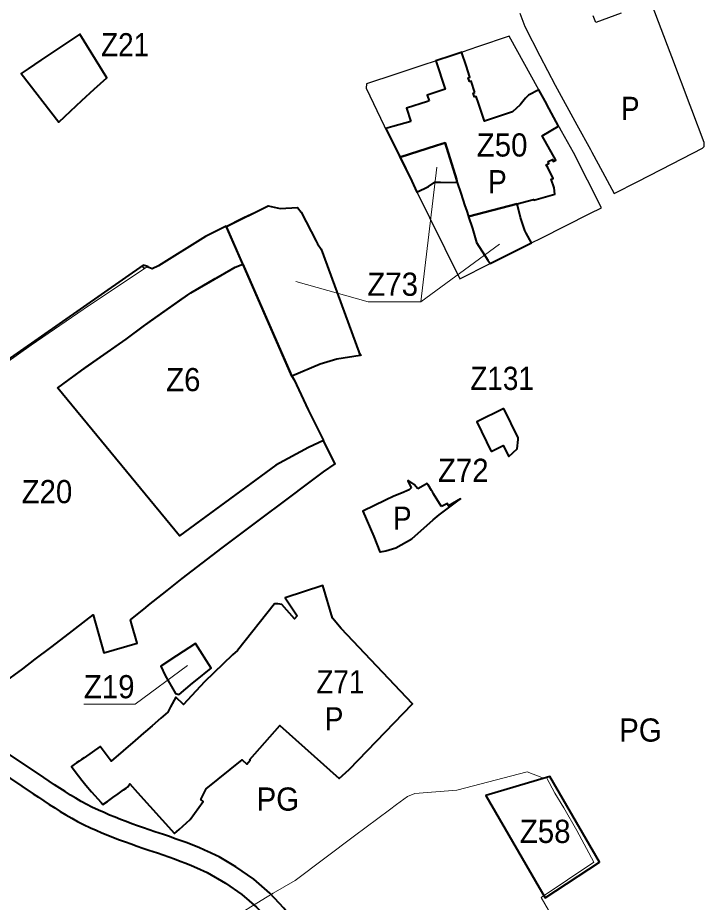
# Model space of a CAD drawing. Extents: x -650276 to -642489, y -1074425 to -1066658.
# Drawn here: x -648043 to -647332, y -1071600 to -1070685 of the extents above; entities that cross this region are included whole.
import ezdxf

# ---------------------------------------------------------------- set-up
doc = ezdxf.new("R2010")
doc.units = 0
doc.header["$LTSCALE"] = 9.6
for name, color, linetype, lineweight in [('1', 7, 'Continuous', 13), ('42', 7, 'Continuous', 25), ('44', 7, 'Continuous', 40), ('45', 7, 'Continuous', 40), ('46', 7, 'Continuous', 13), ('60', 7, 'Continuous', 35)]:
    doc.layers.add(name, color=color, linetype=linetype, lineweight=lineweight)

msp = doc.modelspace()

# ---------------------------------------------------------------- linework, layer by layer
at = {"layer": '1'}
msp.add_line((-647632, -1071487.54), (-647588.48, -1071484.23), dxfattribs=at)
for points in [[(-648084.716, -1071062.607), (-648029.353, -1071023.703), (-647969.116, -1070982.149), (-647909.42, -1070942.63), (-647904.13, -1070944.78), (-647897.76, -1070941.62), (-647848.89, -1070911.21), (-647809.74, -1070891.31), (-647790.016, -1070882.333), (-647783.95, -1070879.58), (-647771.47, -1070882.27), (-647753.81, -1070881.3), (-647749.75, -1070886.1), (-647741.21, -1070902.78), (-647734.48, -1070915.94), (-647732.97, -1070918.87), (-647729.27, -1070924.35), (-647724.603, -1070936.951), (-647701.45, -1070999.4), (-647690.22, -1071030.28), (-647687.41, -1071034.25), (-647688.9, -1071034.18), (-647712.74, -1071037.99), (-647730.17, -1071043.21), (-647759.52, -1071055.67), (-647757.19, -1071059.66), (-647742.64, -1071090.72), (-647726.74, -1071122.48), (-647722.51, -1071130.93), (-647719.73, -1071136.48), (-647714.71, -1071146.51), (-647720.85, -1071150.41), (-647750.34, -1071172.5), (-647756.03, -1071176.76), (-647820.78, -1071225.25), (-647873.25, -1071265.17), (-647888.77, -1071277.56), (-647907.92, -1071292.84), (-647910.73, -1071295.08), (-647926.69, -1071307.81), (-647919.88, -1071332.23), (-647954.38, -1071342)], [(-647954.38, -1071342), (-647965.26, -1071302.86), (-647994.31, -1071325.03), (-648009.31, -1071336.48), (-648025.39, -1071348.76), (-648038.18, -1071358.51), (-648060.01, -1071374.69)], [(-647588.48, -1071484.23), (-647515.87, -1071465.25), (-647498.8, -1071471.94), (-647495.85, -1071471.06), (-647486.94, -1071487.42), (-647477.86, -1071502.65), (-647464.47, -1071526.06), (-647446.68, -1071558.91), (-647501.11, -1071595.45), (-647493.6, -1071608.5)], [(-648086.68, -1071669.2), (-648027.69, -1071748), (-647993.77, -1071766.7), (-647898.22, -1071694.24), (-647875.8, -1071654.22), (-647865.84, -1071646.51), (-647856.11, -1071638.98), (-647845.78, -1071631.97), (-647823.51, -1071618.28), (-647808.56, -1071609.1), (-647801.84, -1071604.97), (-647778.84, -1071590.84), (-647756.17, -1071577.89), (-647694.65, -1071531.5), (-647658.2, -1071504.43), (-647650.97, -1071499.11), (-647639.66, -1071490.78), (-647632, -1071487.54)]]:
    msp.add_lwpolyline(points, dxfattribs=at)
at = {"layer": '42'}
for points in [[(-647523.27, -1070680.11), (-647518.19, -1070693.93), (-647502.59, -1070724.13), (-647486.84, -1070754.54), (-647464.3, -1070795.6), (-647450.23, -1070821.25), (-647448.84, -1070823.79), (-647437.79, -1070844.12), (-647425.58, -1070866.7), (-647401.15, -1070854.25), (-647365.48, -1070835.85), (-647334.27, -1070819.86), (-647332.51, -1070817.97), (-647332.25, -1070813.72), (-647345.18, -1070779.89), (-647346.96, -1070775.41), (-647365.94, -1070725.08), (-647367.67, -1070720.73), (-647377.04, -1070696.22), (-647386.39, -1070671.74)], [(-647418.28, -1070679.89), (-647444.78, -1070689.6), (-647447.31, -1070682.72)], [(-647717.363, -1071306.29), (-647727.368, -1071272.362), (-647766.35, -1071285.11), (-647753.89, -1071303.94), (-647756.67, -1071306.77), (-647769.85, -1071291.91), (-647774.14, -1071291.34), (-647777.4, -1071291.32), (-647815.95, -1071339.71), (-647820.93, -1071344.25), (-647849.86, -1071372.18), (-647867.45, -1071390.95), (-647871.68, -1071395.59), (-647879.76, -1071387.96), (-647885.05, -1071397.88), (-647888.11, -1071403.61), (-647895.29, -1071409.81), (-647904.3, -1071417.58), (-647911.04, -1071423.39), (-647913.31, -1071425.35), (-647921.96, -1071432.81), (-647946.78, -1071454.23), (-647957.906, -1071439.06), (-647974.66, -1071450.62), (-647977.28, -1071452.43), (-647979.88, -1071454.22), (-647982.46, -1071456), (-647985.06, -1071457.79), (-647987.8, -1071459.68), (-647984, -1071465), (-647977.13, -1071474.05), (-647972.76, -1071479)], [(-647710.546, -1071472.023), (-647700.078, -1071462.96), (-647634.524, -1071394.901), (-647708.429, -1071316.821), (-647717.363, -1071306.29)], [(-647803.1, -1071452.66), (-647771.82, -1071417.42), (-647710.546, -1071472.023)], [(-647848.4, -1071482.78), (-647810.97, -1071452.92), (-647806.15, -1071457.48)], [(-647806.15, -1071457.48), (-647802.53, -1071453.19), (-647803.1, -1071452.66)], [(-647972.76, -1071479), (-647967.13, -1071486.01), (-647957.07, -1071497.13), (-647955.14, -1071499.23), (-647950.56, -1071495.85), (-647944.81, -1071491.78), (-647939.31, -1071487.88), (-647933.88, -1071484.04), (-647931.17, -1071482.12), (-647929.26, -1071480.77), (-647927.2, -1071477.54), (-647919.22, -1071486.5), (-647881.16, -1071529.25)], [(-647881.16, -1071529.25), (-647876.27, -1071524.96), (-647864.69, -1071514.65), (-647851.45, -1071495.96), (-647853.77, -1071493.78), (-647848.4, -1071482.78)]]:
    msp.add_lwpolyline(points, dxfattribs=at)
msp.add_lwpolyline([(-647534.33, -1070703.84), (-647567.08, -1070714.8), (-647583.22, -1070720.2), (-647651.82, -1070743.17), (-647682.08, -1070753.29), (-647682.67, -1070757.67), (-647663.71, -1070796.77), (-647585.55, -1070954.94), (-647553.94, -1070939.11), (-647532.58, -1070928.392), (-647511.37, -1070917.79), (-647501.26, -1070912.72), (-647450.8, -1070887.42), (-647438.82, -1070881.43), (-647467.89, -1070824.15), (-647480.13, -1070802.09), (-647503.76, -1070759.31)], close=True, dxfattribs=at)
at = {"layer": '44'}
for points in [[(-647834.953, -1071553.406), (-647837.929, -1071551.872), (-647843.891, -1071549), (-647849.898, -1071546.282), (-647855.937, -1071543.707), (-647861.998, -1071541.254), (-647868.073, -1071538.911), (-647874.155, -1071536.658), (-647880.233, -1071534.48), (-647886.305, -1071532.36), (-647892.363, -1071530.282), (-647901.28, -1071527.249), (-647907.294, -1071525.204), (-647913.282, -1071523.152), (-647919.238, -1071521.081), (-647925.157, -1071518.976), (-647931.035, -1071516.824), (-647936.866, -1071514.613), (-647942.644, -1071512.329), (-647948.363, -1071509.96), (-647954.016, -1071507.496), (-647959.792, -1071504.833), (-647966.547, -1071501.883), (-647972.035, -1071499.009), (-647977.67, -1071495.885), (-647983.266, -1071492.628), (-647988.829, -1071489.259), (-647994.366, -1071485.79), (-647999.887, -1071482.241), (-648005.399, -1071478.627), (-648010.917, -1071474.963), (-648016.446, -1071471.268), (-648063.593, -1071439.723)], [(-648074.86, -1071456.248), (-648027.562, -1071487.894), (-648022.005, -1071491.607), (-648016.415, -1071495.321), (-648010.777, -1071499.017), (-648005.082, -1071502.678), (-647999.319, -1071506.287), (-647993.478, -1071509.826), (-647987.55, -1071513.275), (-647981.525, -1071516.615), (-647975.201, -1071519.929), (-647967.982, -1071523.081), (-647962.2, -1071525.746), (-647956.187, -1071528.368), (-647950.146, -1071530.869), (-647944.088, -1071533.263), (-647938.019, -1071535.566), (-647931.945, -1071537.788), (-647925.874, -1071539.949), (-647919.808, -1071542.058), (-647913.756, -1071544.132), (-647907.72, -1071546.185), (-647898.827, -1071549.208), (-647892.847, -1071551.26), (-647886.903, -1071553.336), (-647881.001, -1071555.45), (-647875.147, -1071557.619), (-647869.348, -1071559.856), (-647863.611, -1071562.177), (-647857.944, -1071564.594), (-647847.103, -1071569.497)], [(-647725.629, -1071678.373), (-647735.352, -1071657.117), (-647741.34, -1071644.028), (-647753.065, -1071625.201), (-647767.784, -1071606.225), (-647782.408, -1071590.847), (-647798.911, -1071576.526), (-647817.375, -1071563.458), (-647834.953, -1071553.406)], [(-647847.103, -1071569.497), (-647828.141, -1071580.34), (-647811.272, -1071592.28), (-647796.24, -1071605.324), (-647782.97, -1071619.278)]]:
    msp.add_lwpolyline(points, dxfattribs=at)
at = {"layer": '45'}
msp.add_line((-647914.73, -1070941.682), (-647912.347, -1070944.065), dxfattribs=at)
msp.add_line((-647914.73, -1070941.682), (-647912.347, -1070944.065), dxfattribs=at)
for points in [[(-648032.601, -1070737.472), (-648039.82, -1070742.33), (-648000.85, -1070792.88), (-647994.63, -1070787.05), (-647982.89, -1070776.05), (-647976.97, -1070770.51), (-647964.21, -1070758.77), (-647951.11, -1070746.78), (-647979.17, -1070701.65), (-648008.28, -1070720.96), (-648009.29, -1070721.79), (-648019.49, -1070728.65)], [(-647827.363, -1070900.725), (-647783.95, -1070879.58), (-647771.47, -1070882.27), (-647753.81, -1070881.3), (-647749.75, -1070886.1), (-647734.48, -1070915.94), (-647732.97, -1070918.87), (-647729.27, -1070924.35), (-647701.45, -1070999.4), (-647688.9, -1071034.18), (-647712.74, -1071037.99), (-647730.17, -1071043.21), (-647759.52, -1071055.67)], [(-647827.363, -1070900.725), (-647783.95, -1070879.58), (-647771.47, -1070882.27), (-647753.81, -1070881.3), (-647749.75, -1070886.1), (-647734.48, -1070915.94), (-647732.97, -1070918.87), (-647729.27, -1070924.35), (-647701.45, -1070999.4), (-647688.9, -1071034.18), (-647712.74, -1071037.99), (-647730.17, -1071043.21), (-647759.52, -1071055.67)], [(-648001.766, -1071068.02), (-648001.922, -1071067.83), (-647973.304, -1071046.814), (-647930.96, -1071017.383), (-647912.11, -1071003.11), (-647906.9, -1070999.39), (-647875.248, -1070977.173), (-647864.03, -1070969.3), (-647843.928, -1070957.692), (-647818.33, -1070942.91), (-647810.243, -1070939.825), (-647759.52, -1071055.67), (-647757.19, -1071059.66), (-647742.64, -1071090.72), (-647726.74, -1071122.48), (-647742.35, -1071129.43), (-647775.982, -1071148.001), (-647775.982, -1071148.001), (-647875.939, -1071221.104)], [(-647974.66, -1071450.62), (-647977.28, -1071452.43), (-647979.88, -1071454.22), (-647982.46, -1071456), (-647985.06, -1071457.79), (-647987.8, -1071459.68), (-647984, -1071465), (-647977.13, -1071474.05), (-647972.76, -1071479), (-647967.13, -1071486.01), (-647957.07, -1071497.13), (-647955.14, -1071499.23), (-647950.56, -1071495.85), (-647944.81, -1071491.78), (-647939.31, -1071487.88), (-647933.88, -1071484.04), (-647931.17, -1071482.12), (-647929.26, -1071480.77), (-647927.2, -1071477.54), (-647919.22, -1071486.5), (-647881.16, -1071529.25), (-647876.27, -1071524.96), (-647864.69, -1071514.65), (-647851.45, -1071495.96), (-647853.77, -1071493.78), (-647848.4, -1071482.78), (-647810.97, -1071452.92), (-647806.15, -1071457.48), (-647802.53, -1071453.19), (-647803.1, -1071452.66), (-647771.82, -1071417.42), (-647710.546, -1071472.023), (-647700.078, -1071462.96), (-647634.524, -1071394.901), (-647708.429, -1071316.821), (-647717.363, -1071306.29), (-647727.368, -1071272.362), (-647766.35, -1071285.11), (-647753.89, -1071303.94), (-647756.67, -1071306.77), (-647769.85, -1071291.91), (-647774.14, -1071291.34), (-647777.4, -1071291.32), (-647815.95, -1071339.71), (-647820.93, -1071344.25), (-647849.86, -1071372.18), (-647867.45, -1071390.95), (-647871.68, -1071395.59), (-647879.76, -1071387.96), (-647885.05, -1071397.88), (-647888.11, -1071403.61), (-647895.29, -1071409.81), (-647904.3, -1071417.58), (-647911.04, -1071423.39), (-647913.31, -1071425.35), (-647921.96, -1071432.81), (-647946.78, -1071454.23), (-647957.906, -1071439.06)], [(-647974.66, -1071450.62), (-647977.28, -1071452.43), (-647979.88, -1071454.22), (-647982.46, -1071456), (-647985.06, -1071457.79), (-647987.8, -1071459.68), (-647984, -1071465), (-647977.13, -1071474.05), (-647972.76, -1071479), (-647967.13, -1071486.01), (-647957.07, -1071497.13), (-647955.14, -1071499.23), (-647950.56, -1071495.85), (-647944.81, -1071491.78), (-647939.31, -1071487.88), (-647933.88, -1071484.04), (-647931.17, -1071482.12), (-647929.26, -1071480.77), (-647927.2, -1071477.54), (-647919.22, -1071486.5), (-647881.16, -1071529.25), (-647876.27, -1071524.96), (-647864.69, -1071514.65), (-647851.45, -1071495.96), (-647853.77, -1071493.78), (-647848.4, -1071482.78), (-647810.97, -1071452.92), (-647806.15, -1071457.48), (-647802.53, -1071453.19), (-647803.1, -1071452.66), (-647771.82, -1071417.42), (-647710.546, -1071472.023), (-647700.078, -1071462.96), (-647634.524, -1071394.901), (-647708.429, -1071316.821), (-647717.363, -1071306.29), (-647727.368, -1071272.362), (-647766.35, -1071285.11), (-647753.89, -1071303.94), (-647756.67, -1071306.77), (-647769.85, -1071291.91), (-647774.14, -1071291.34), (-647777.4, -1071291.32), (-647815.95, -1071339.71), (-647820.93, -1071344.25), (-647849.86, -1071372.18), (-647867.45, -1071390.95), (-647871.68, -1071395.59), (-647879.76, -1071387.96), (-647885.05, -1071397.88), (-647888.11, -1071403.61), (-647895.29, -1071409.81), (-647904.3, -1071417.58), (-647911.04, -1071423.39), (-647913.31, -1071425.35), (-647921.96, -1071432.81), (-647946.78, -1071454.23), (-647957.906, -1071439.06)], [(-647879.09, -1071345.3), (-647895.37, -1071355.96), (-647890.7, -1071365.52), (-647880.14, -1071384.32), (-647876.34, -1071385.2), (-647862.25, -1071373.55), (-647859.44, -1071371.23), (-647843.23, -1071357.82), (-647859.31, -1071332.34)], [(-647879.09, -1071345.3), (-647895.37, -1071355.96), (-647890.7, -1071365.52), (-647880.14, -1071384.32), (-647876.34, -1071385.2), (-647862.25, -1071373.55), (-647859.44, -1071371.23), (-647843.23, -1071357.82), (-647859.31, -1071332.34)], [(-647497.04, -1071595.66), (-647440.67, -1071558.93), (-647492.3, -1071470), (-647495.85, -1071471.06), (-647558.654, -1071489.738)], [(-647497.04, -1071595.66), (-647440.67, -1071558.93), (-647492.3, -1071470), (-647495.85, -1071471.06), (-647558.654, -1071489.738)]]:
    msp.add_lwpolyline(points, close=True, dxfattribs=at)
for points in [[(-647569.92, -1070762.24), (-647573.88, -1070750.25), (-647575.58, -1070750.83), (-647576.81, -1070746.86), (-647575.09, -1070746.33), (-647578.79, -1070734.33), (-647583.38, -1070720.9), (-647583.22, -1070720.2), (-647593.6, -1070723.68), (-647610.33, -1070729.28), (-647600.53, -1070758.65), (-647619.2, -1070764.85), (-647617.36, -1070770.69)], [(-647636.12, -1070792.13), (-647654.89, -1070797.23), (-647662.26, -1070799.23), (-647650.908, -1070822.34), (-647647.405, -1070829.08), (-647609.58, -1070817.06), (-647600.8, -1070814.27), (-647588.89, -1070851.67), (-647588.4, -1070855.25), (-647584.6, -1070866.3), (-647580.22, -1070879.3), (-647578.703, -1070883.851), (-647578.703, -1070883.851), (-647576.469, -1070890.564), (-647526.13, -1070877.41), (-647509.1, -1070872.96), (-647508.96, -1070873.41), (-647487.16, -1070867.32), (-647487.91, -1070860.91), (-647490.92, -1070851.82), (-647488.8, -1070851.12), (-647494.1, -1070840.58), (-647495.93, -1070836.86), (-647493.16, -1070835.5), (-647494.03, -1070833.64), (-647489.55, -1070831.53), (-647488.75, -1070833.37), (-647485.9, -1070832), (-647500.07, -1070806.87), (-647500.07, -1070806.87), (-647483.16, -1070797.07), (-647492.81, -1070779.18), (-647492.81, -1070779.18), (-647497.227, -1070771.165), (-647503.76, -1070759.31), (-647514.49, -1070764.93), (-647517.61, -1070767.89), (-647523.07, -1070774.86), (-647531.05, -1070782.23), (-647560.06, -1070791.72), (-647566.26, -1070773.148)], [(-647570.27, -1070766.86), (-647571.63, -1070762.82), (-647569.92, -1070762.24)], [(-647617.36, -1070770.69), (-647619.12, -1070771.28), (-647640.66, -1070778.47), (-647636.12, -1070792.13)], [(-647566.26, -1070773.148), (-647568.55, -1070766.29), (-647570.27, -1070766.86)], [(-647588.4, -1070855.25), (-647588.89, -1070851.67), (-647600.8, -1070814.27), (-647609.58, -1070817.06), (-647647.405, -1070829.08)], [(-647588.4, -1070855.25), (-647588.89, -1070851.67), (-647600.8, -1070814.27), (-647609.58, -1070817.06), (-647647.405, -1070829.08)], [(-647647.405, -1070829.08), (-647635.11, -1070853.786), (-647629.92, -1070865.35), (-647618.01, -1070859.42), (-647611.3, -1070854.9), (-647605.64, -1070854.99), (-647588.4, -1070855.25)], [(-647647.405, -1070829.08), (-647635.11, -1070853.786), (-647629.92, -1070865.35), (-647618.01, -1070859.42), (-647611.3, -1070854.9), (-647605.64, -1070854.99), (-647588.4, -1070855.25)], [(-647511.37, -1070917.79), (-647516.66, -1070907.8), (-647518.12, -1070905.05), (-647522.74, -1070891.48), (-647526.13, -1070877.41), (-647576.469, -1070890.564)], [(-647576.469, -1070890.564), (-647576.43, -1070890.68), (-647572.32, -1070902.72), (-647568.2, -1070917.54), (-647556.52, -1070935.59), (-647553.94, -1070939.11)], [(-648060.01, -1071374.69), (-648038.18, -1071358.51), (-648025.39, -1071348.76), (-648009.31, -1071336.48), (-647994.31, -1071325.03), (-647965.26, -1071302.86), (-647954.38, -1071342), (-647919.88, -1071332.23), (-647925.6, -1071311.69), (-647926.69, -1071307.81), (-647910.73, -1071295.08), (-647907.92, -1071292.84), (-647888.77, -1071277.56), (-647873.25, -1071265.17), (-647831.565, -1071233.455), (-647801.178, -1071210.742), (-647756.03, -1071176.76), (-647750.34, -1071172.5), (-647726.56, -1071154.68), (-647714.71, -1071146.51), (-647714.71, -1071146.51), (-647719.73, -1071136.48), (-647726.74, -1071122.48), (-647742.35, -1071129.43), (-647775.982, -1071148.001), (-647808.402, -1071171.711), (-647848.51, -1071201.045), (-647875.939, -1071221.104), (-648001.766, -1071068.02), (-648001.922, -1071067.83), (-647977.41, -1071049.74), (-647930.96, -1071017.383), (-647911.838, -1071002.919), (-647912.11, -1071003.11), (-647864.29, -1070969.503), (-647838.842, -1070954.778), (-647818.33, -1070942.91), (-647810.243, -1070939.825), (-647827.527, -1070900.351), (-647848.89, -1070911.21), (-647897.76, -1070941.62), (-647904.13, -1070944.78), (-647909.42, -1070942.63), (-647908.63, -1070942.1), (-647913.45, -1070940.79), (-648062.53, -1071044.59)], [(-647553.94, -1070939.11), (-647553.94, -1070939.11), (-647550.59, -1070937.45), (-647533.31, -1070928.79), (-647511.37, -1070917.79)], [(-647539.818, -1071089.2), (-647568.01, -1071102.98), (-647553.01, -1071133.68)], [(-647525.1, -1071121.25), (-647524.95, -1071119.68), (-647539.817, -1071089.199)], [(-647553.01, -1071133.68), (-647540.48, -1071127.55), (-647534.851, -1071139.015), (-647526.04, -1071130.94), (-647525.1, -1071121.25)], [(-647629.09, -1071172.4), (-647632.93, -1071167.71), (-647638.46, -1071163.89), (-647639.32, -1071164.22), (-647635.93, -1071171.22)], [(-647629.09, -1071172.4), (-647632.93, -1071167.71), (-647638.46, -1071163.89), (-647639.32, -1071164.22), (-647635.93, -1071171.22)], [(-647635.93, -1071171.22), (-647637.87, -1071173.29), (-647646.09, -1071176.68), (-647653.85, -1071179.87), (-647662.634, -1071183.968)], [(-647635.93, -1071171.22), (-647637.87, -1071173.29), (-647646.09, -1071176.68), (-647653.85, -1071179.87), (-647662.634, -1071183.968)], [(-647612.695, -1071177.542), (-647613.91, -1071175.57), (-647614.732, -1071174.222), (-647618.446, -1071168.166), (-647618.469, -1071168.129), (-647618.77, -1071167.64), (-647619.264, -1071166.832), (-647619.34, -1071166.709), (-647628.39, -1071172.05), (-647629.09, -1071172.4)], [(-647612.695, -1071177.542), (-647613.91, -1071175.57), (-647614.732, -1071174.222), (-647618.446, -1071168.166), (-647618.469, -1071168.129), (-647618.77, -1071167.64), (-647619.264, -1071166.832), (-647619.34, -1071166.709), (-647628.39, -1071172.05), (-647629.09, -1071172.4)], [(-647662.634, -1071183.968), (-647686.01, -1071195.35), (-647686.01, -1071195.35)], [(-647662.634, -1071183.968), (-647686.01, -1071195.35), (-647686.01, -1071195.35)], [(-647674.6, -1071221.71), (-647668.226, -1071237.571), (-647667.77, -1071237.5), (-647661.99, -1071236.62), (-647658.78, -1071235.63), (-647651.93, -1071233.57), (-647635.17, -1071224.18), (-647613.09, -1071204.33), (-647607.02, -1071199.34), (-647584.92, -1071182.54), (-647597.164, -1071189.857), (-647598.215, -1071187.608), (-647604.576, -1071190.781)], [(-647674.6, -1071221.71), (-647668.226, -1071237.571), (-647667.77, -1071237.5), (-647661.99, -1071236.62), (-647658.78, -1071235.63), (-647651.93, -1071233.57), (-647635.17, -1071224.18), (-647613.09, -1071204.33), (-647607.02, -1071199.34), (-647584.92, -1071182.54), (-647597.164, -1071189.857), (-647598.215, -1071187.608), (-647604.576, -1071190.781)], [(-647604.576, -1071190.781), (-647604.888, -1071190.272), (-647612.695, -1071177.542)], [(-647604.576, -1071190.781), (-647604.888, -1071190.272), (-647612.695, -1071177.542)], [(-647686.01, -1071195.35), (-647686.01, -1071195.35), (-647674.6, -1071221.71)], [(-647686.01, -1071195.35), (-647686.01, -1071195.35), (-647674.6, -1071221.71)]]:
    msp.add_lwpolyline(points, dxfattribs=at)
at = {"layer": '46'}
for points in [[(-647544.337, -1070919.163), (-647625.809, -1070978.773), (-647609.46, -1070839.305), (-647625.809, -1070978.773), (-647680.348, -1070978.773), (-647755.299, -1070957.715)], [(-647544.337, -1070919.163), (-647625.809, -1070978.773), (-647609.46, -1070839.305), (-647625.809, -1070978.773), (-647680.348, -1070978.773), (-647755.299, -1070957.715)], [(-647974.97, -1071395.111), (-647921.786, -1071395.111), (-647867.57, -1071355.322)], [(-647974.97, -1071395.111), (-647921.786, -1071395.111), (-647867.57, -1071355.322)]]:
    msp.add_lwpolyline(points, dxfattribs=at)

# ---------------------------------------------------------------- texts
for s, width, p in [('Z21', 0.9, (-647957.11, -1070724.677)), ('Z50', 0.95, (-647567.967, -1070828.405)), ('Z50', 0.95, (-647567.967, -1070828.405)), ('Z73', 0.95, (-647681.324, -1070972.53)), ('Z73', 0.95, (-647681.324, -1070972.53)), ('Z6', 0.95, (-647889.738, -1071071.271)), ('Z131', 0.9, (-647574.644, -1071069.985)), ('Z72', 0.95, (-647608.212, -1071165.192)), ('Z72', 0.95, (-647608.212, -1071165.192)), ('Z20', 0.95, (-648039.444, -1071187.201)), ('Z19', 0.95, (-647974.958, -1071389.14)), ('Z19', 0.95, (-647974.958, -1071389.14)), ('Z71', 0.9, (-647734.152, -1071384.125)), ('Z71', 0.9, (-647734.152, -1071384.125)), ('Z58', 0.95, (-647523.363, -1071538.888)), ('Z58', 0.95, (-647523.363, -1071538.888))]:
    msp.add_text(s, height=24, dxfattribs=dict(at, width=width)).set_placement(p)
at = {"layer": '60'}
for s, width, p in [('P', 0.9, (-647418.572, -1070790.564)), ('P', 0.9, (-647418.572, -1070790.564)), ('P', 0.9, (-647556.162, -1070866.47)), ('P', 0.9, (-647556.162, -1070866.47)), ('P', 0.9, (-647654.706, -1071214.743)), ('P', 0.9, (-647654.706, -1071214.743)), ('P', 0.9, (-647725.36, -1071422.368)), ('P', 0.9, (-647725.36, -1071422.368)), ('PG', 0.95, (-647420.449, -1071434.013)), ('PG', 0.95, (-647420.449, -1071434.013)), ('PG', 0.95, (-647796.031, -1071505.454)), ('PG', 0.95, (-647796.031, -1071505.454))]:
    msp.add_text(s, height=24, dxfattribs=dict(at, width=width)).set_placement(p)

doc.saveas('drawing.dxf')
